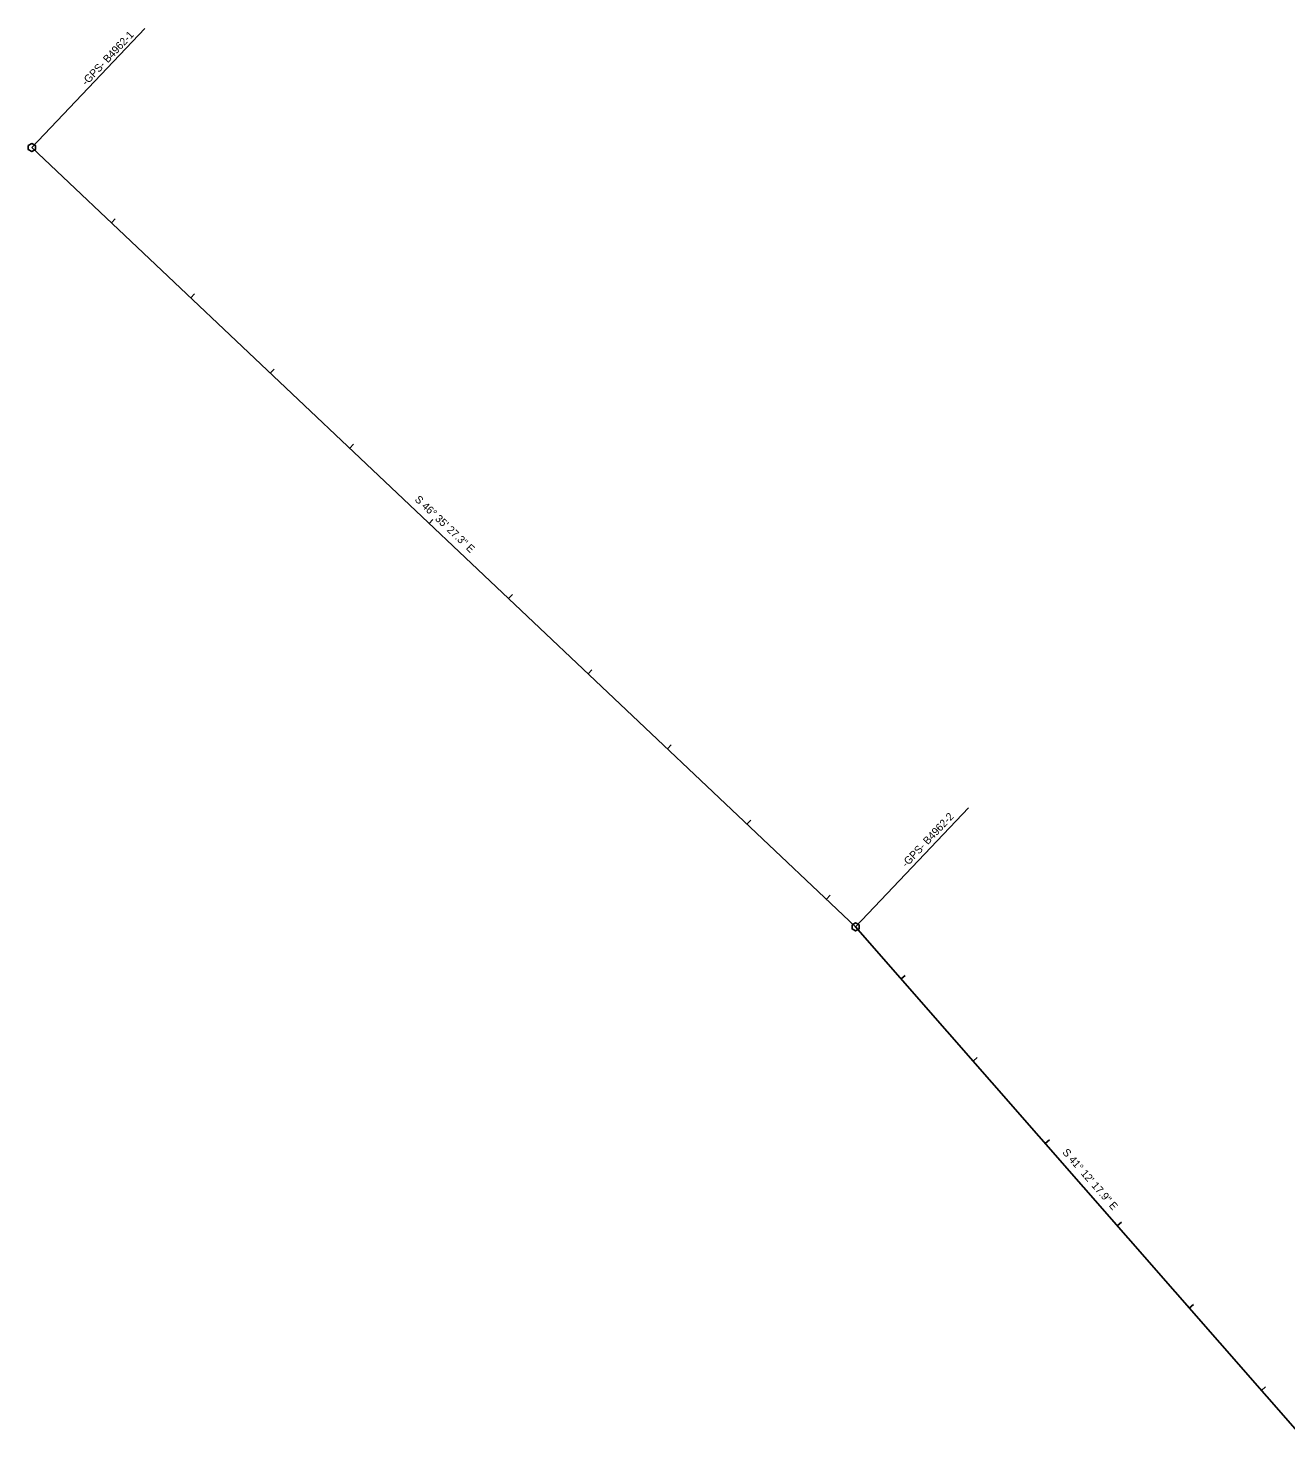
# Model space of a CAD drawing. Extents: x 1977096 to 1980486, y 845025 to 848427.
# Drawn here: x 1977096 to 1978245, y 847130 to 848427 of the extents above; entities that cross this region are included whole.
import ezdxf

# ---------------------------------------------------------------- set-up
doc = ezdxf.new("R2010")
doc.units = 0
for name, color, linetype in [('CTL GPS Vertical CELL', 7, 'Continuous'), ('Exist Horizontal Baseline Alignment', 7, 'Continuous'), ('Exist Horizontal Baseline Alignment Direction Label', 7, 'Continuous'), ('Exist Horizontal Baseline Alignment Station Label', 7, 'Continuous'), ('Exist Horizontal Baseline Alignment Tick small', 7, 'Continuous')]:
    doc.layers.add(name, color=color, linetype=linetype)

msp = doc.modelspace()

# ---------------------------------------------------------------- linework, layer by layer
at = {"layer": 'CTL GPS Vertical CELL'}
for p, q in [((1977098.9, 848318.3), (1977098.9, 848318.3)), ((1977852.1, 847605.8), (1977852.1, 847605.8))]:
    msp.add_line(p, q, dxfattribs=at)
for points in [[(1977095.6, 848320.2), (1977098.9, 848322), (1977102.1, 848320.2), (1977102.1, 848316.5), (1977098.8, 848314.6), (1977095.6, 848316.4)], [(1977848.9, 847607.7), (1977852.1, 847609.5), (1977855.4, 847607.7), (1977855.3, 847604), (1977852.1, 847602.1), (1977848.9, 847603.9)]]:
    msp.add_lwpolyline(points, close=True, dxfattribs=at)
at = {"layer": 'Exist Horizontal Baseline Alignment'}
for p, q in [((1977098.9, 848318.3), (1977852.1, 847605.8)), ((1977852.1, 847605.8), (1978268.9, 847129.8))]:
    msp.add_line(p, q, dxfattribs=at)
at = {"layer": 'Exist Horizontal Baseline Alignment Station Label'}
for p, q in [((1977098.9, 848318.3), (1977202, 848427.3)), ((1977852.1, 847605.8), (1977955.2, 847714.7))]:
    msp.add_line(p, q, dxfattribs=at)
at = {"layer": 'Exist Horizontal Baseline Alignment Tick small'}
for p, q in [((1977098.9, 848318.3), (1977102.3, 848321.9)), ((1977171.5, 848249.6), (1977175, 848253.2)), ((1977244.2, 848180.8), (1977247.6, 848184.5)), ((1977316.8, 848112.1), (1977320.3, 848115.8)), ((1977389.5, 848043.4), (1977392.9, 848047)), ((1977462.1, 847974.7), (1977465.5, 847978.3)), ((1977534.8, 847906), (1977538.2, 847909.6)), ((1977607.4, 847837.2), (1977610.8, 847840.9)), ((1977680, 847768.5), (1977683.5, 847772.2)), ((1977752.7, 847699.8), (1977756.1, 847703.4)), ((1977825.3, 847631.1), (1977828.8, 847634.7)), ((1977893.7, 847558.2), (1977897.5, 847561.5)), ((1977959.6, 847483), (1977963.3, 847486.3)), ((1978025.5, 847407.8), (1978029.2, 847411.1)), ((1978091.3, 847332.5), (1978095.1, 847335.8)), ((1978157.2, 847257.3), (1978161, 847260.6)), ((1978223.1, 847182.1), (1978226.8, 847185.4))]:
    msp.add_line(p, q, dxfattribs=at)

# ---------------------------------------------------------------- texts
at = {"layer": 'Exist Horizontal Baseline Alignment Direction Label'}
for s, rotation, p in [('S 46%%d 35\' 27.3" E', 316.5909, (1977448.4, 847995.9)), ('S 41%%d 12\' 17.9" E', 311.205, (1978040.7, 847399.4))]:
    msp.add_text(s, height=7, rotation=rotation, dxfattribs=at).set_placement(p)
at = {"layer": 'Exist Horizontal Baseline Alignment Station Label'}
for s, p in [('-GPS- B4962-1', (1977148.6, 848374.4)), ('-GPS- B4962-2   ', (1977898.4, 847659.7))]:
    msp.add_text(s, height=7, rotation=46.5909, dxfattribs=at).set_placement(p)

doc.saveas('drawing.dxf')
